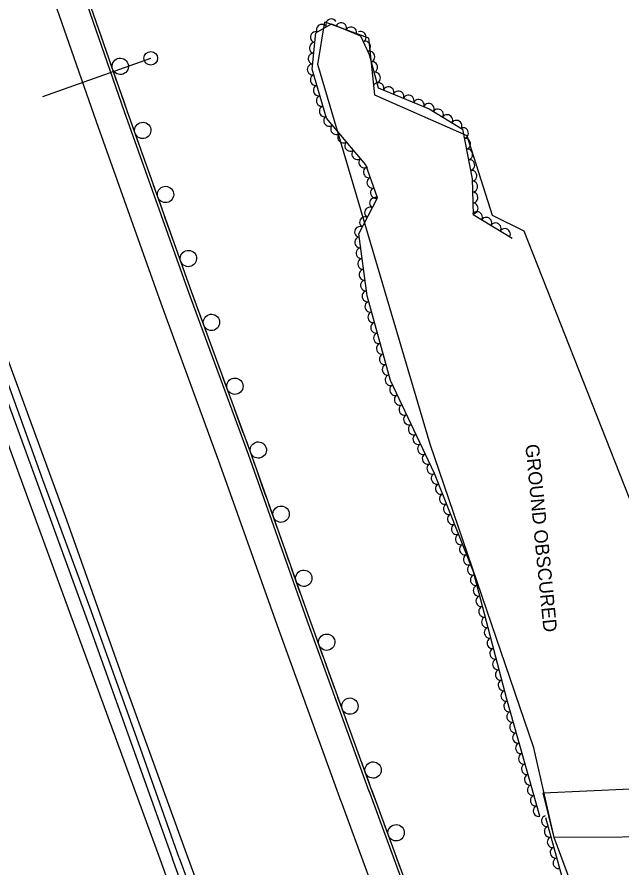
# Model space of a CAD drawing. Extents: x 1746719 to 1766531, y 631721 to 662391.
# Drawn here: x 1754457 to 1754679.2, y 649456.3 to 649768.8 of the extents above; entities that cross this region are included whole.
import ezdxf

# ---------------------------------------------------------------- set-up
doc = ezdxf.new("R2010")
doc.units = 0
for name, color, linetype in [('SURVEY - AERIAL SURVEY - Photo Control - Points - Elevations', 7, 'Continuous'), ('SURVEY - AERIAL SURVEY - Photo Control - Points - Locators', 7, 'Continuous'), ('SURVEY - AERIAL SURVEY - Photo Control - Points - Numbers', 7, 'Continuous'), ('SURVEY - AERIAL SURVEY - Photo Control with Text', 7, 'Continuous'), ('SURVEY - CONTROL - Grid', 7, 'Continuous')]:
    doc.layers.add(name, color=color, linetype=linetype)

msp = doc.modelspace()

# ---------------------------------------------------------------- linework, layer by layer
at = {"layer": 'SURVEY - AERIAL SURVEY - Photo Control - Points - Elevations'}
for points in [[(1754372.91, 649841.05), (1754399.86, 649762.15), (1754431.05, 649673.76), (1754457.17, 649602.22), (1754509.57, 649459.27)], [(1754519.88, 649459.84), (1754496.93, 649522.97), (1754475.36, 649583.78), (1754453.6, 649643.04), (1754429.6, 649710.4), (1754402.92, 649787.27), (1754386.52, 649835.23)], [(1754576.27, 649480.33), (1754553.4, 649543.24), (1754531.8, 649604.15), (1754510.02, 649663.45), (1754486.2, 649730.31), (1754460.8, 649803.48)], [(1754586.6, 649484.09), (1754563.76, 649546.96), (1754542.15, 649607.89), (1754520.37, 649667.19), (1754496.58, 649733.96), (1754474.48, 649797.64)], [(1755115.35, 648210.44), (1755101.05, 648241.68), (1755075.7, 648298.73), (1755049.35, 648357.31), (1755030.85, 648399.58), (1755014.73, 648435.52), (1754992.75, 648485.36), (1754969, 648539.7), (1754947.21, 648588.87), (1754915.3, 648661.1), (1754893.71, 648710.14), (1754872.45, 648759.46), (1754844.58, 648825.55), (1754823.17, 648877.77), (1754798.13, 648938.26), (1754769.55, 649009.24), (1754747.62, 649063.55), (1754724.17, 649123.36), (1754701.64, 649181.06), (1754680.19, 649235.39), (1754656.46, 649296.06), (1754637.62, 649345.88), (1754614.74, 649407.39), (1754586.53, 649484.29)], [(1755104.99, 648205.74), (1755065.66, 648294.24), (1755039.29, 648352.85), (1755020.79, 648395.13), (1755004.68, 648431.05), (1754982.68, 648480.94), (1754958.93, 648535.27), (1754937.15, 648584.41), (1754905.24, 648656.66), (1754883.62, 648705.74), (1754862.33, 648755.14), (1754834.42, 648821.33), (1754813, 648873.58), (1754787.94, 648934.1), (1754759.35, 649005.13), (1754737.4, 649059.49), (1754713.93, 649119.35), (1754691.4, 649177.04), (1754669.95, 649231.36), (1754646.2, 649292.11), (1754627.32, 649342.01), (1754604.42, 649403.58), (1754576.2, 649480.5)], [(1754509.57, 649459.27), (1754525.94, 649413.69), (1754546.16, 649358.93), (1754566.55, 649304.57), (1754591.05, 649240.64), (1754617.15, 649173.14), (1754643.97, 649105.23), (1754664.59, 649052.46), (1754685.99, 648998.63), (1754712.43, 648932.12), (1754736.99, 648873.55), (1754758.79, 648818.39), (1754779.59, 648768.19), (1754804.48, 648710.45), (1754831.65, 648646.67), (1754855.43, 648592.01), (1754875.72, 648544.86), (1754897.72, 648495.75)], [(1755048.84, 648185.15), (1755036.33, 648212.5), (1755010.89, 648269.75), (1754984.45, 648328.51), (1754965.93, 648370.82), (1754949.86, 648406.67), (1754927.74, 648456.82), (1754904.02, 648511.09), (1754882.28, 648560.14), (1754850.34, 648632.45), (1754828.62, 648681.78), (1754807.13, 648731.61), (1754779.02, 648798.3), (1754757.53, 648850.72), (1754732.4, 648911.42), (1754703.7, 648982.69), (1754681.66, 649037.3), (1754658.05, 649097.48), (1754635.55, 649155.11), (1754614.11, 649209.42), (1754590.2, 649270.57), (1754571.14, 649320.94), (1754548.14, 649382.79), (1754519.88, 649459.84)]]:
    msp.add_lwpolyline(points, dxfattribs=at)
at = {"layer": 'SURVEY - AERIAL SURVEY - Photo Control - Points - Locators'}
for points in [[(1754643.48, 649690.19), (1754713.8, 649511.77), (1754691.9, 649508.23), (1754704.69, 649467.42), (1754654.55, 649467.07), (1754647.16, 649500.04), (1754608.95, 649611.71), (1754567.7, 649751.34), (1754570.28, 649767.07), (1754586.25, 649761.13), (1754588.45, 649740.16), (1754622.5, 649725.22), (1754631.78, 649695.88), (1754643.48, 649690.19)], [(1754682.93, 649401.74), (1754668.94, 649428.44), (1754654.55, 649467.07), (1754654.55, 649467.07), (1754650.58, 649483.59), (1754698.72, 649485.75)]]:
    msp.add_lwpolyline(points, dxfattribs=at)
at = {"layer": 'SURVEY - AERIAL SURVEY - Photo Control - Points - Numbers'}
for points in [[(1754379.58, 649838.2), (1754396.39, 649787.83), (1754417.71, 649728.02), (1754438.48, 649668.45), (1754465.02, 649595.86), (1754484.29, 649542.97), (1754514.24, 649459.31)], [(1754516.62, 649459.65), (1754501.04, 649503.67), (1754483.8, 649551.83), (1754466.56, 649598.63), (1754446.68, 649653.43), (1754425.68, 649712.01), (1754407.27, 649765.12), (1754389.44, 649816.85), (1754382.87, 649836.79)], [(1754587.54, 649484.43), (1754564.7, 649547.3), (1754543.09, 649608.22), (1754521.31, 649667.53), (1754497.52, 649734.29), (1754475.72, 649797.1)], [(1754488.06, 649761.54), (1754486.52, 649765.98)], [(1754489.6, 649757.1), (1754488.06, 649761.54)], [(1754493.67, 649745.39), (1754490.65, 649754.08)], [(1754496.26, 649737.92), (1754494.72, 649742.36)], [(1754497.81, 649733.48), (1754497.52, 649734.29), (1754496.26, 649737.92)], [(1754501.97, 649721.81), (1754498.88, 649730.47)], [(1754504.62, 649714.36), (1754503.04, 649718.79)], [(1754506.2, 649709.94), (1754504.62, 649714.36)], [(1754510.36, 649698.26), (1754507.27, 649706.92)], [(1754513.01, 649690.81), (1754511.43, 649695.24)], [(1754514.59, 649686.39), (1754513.01, 649690.81)], [(1754518.75, 649674.71), (1754515.66, 649683.37)], [(1754521.41, 649667.27), (1754521.31, 649667.53), (1754519.82, 649671.69)], [(1754523.03, 649662.85), (1754521.41, 649667.27)], [(1754527.3, 649651.21), (1754524.13, 649659.85)], [(1754530.02, 649643.8), (1754528.4, 649648.21)], [(1754531.64, 649639.39), (1754530.02, 649643.8)], [(1754535.92, 649627.75), (1754532.75, 649636.38)], [(1754538.64, 649620.33), (1754537.02, 649624.74)], [(1754540.26, 649615.92), (1754538.64, 649620.33)], [(1754544.49, 649604.26), (1754543.09, 649608.22), (1754541.37, 649612.91)], [(1754547.13, 649596.82), (1754545.56, 649601.25)], [(1754548.71, 649592.39), (1754547.13, 649596.82)], [(1754552.85, 649580.7), (1754549.78, 649589.37)], [(1754555.49, 649573.26), (1754553.92, 649577.69)], [(1754557.06, 649568.83), (1754555.49, 649573.26)], [(1754561.21, 649557.14), (1754558.13, 649565.81)], [(1754563.85, 649549.69), (1754562.28, 649554.12)], [(1754565.44, 649545.27), (1754564.7, 649547.3), (1754563.85, 649549.69)], [(1754569.67, 649533.61), (1754566.53, 649542.26)], [(1754572.37, 649526.19), (1754570.76, 649530.61)], [(1754573.97, 649521.77), (1754572.37, 649526.19)], [(1754578.21, 649510.12), (1754575.07, 649518.77)], [(1754580.91, 649502.69), (1754579.3, 649507.11)], [(1754582.51, 649498.28), (1754580.91, 649502.69)], [(1754586.75, 649486.62), (1754583.61, 649495.27)], [(1754825.74, 648874.19), (1754799.05, 648938.64), (1754770.48, 649009.61), (1754748.55, 649063.92), (1754725.1, 649123.72), (1754702.57, 649181.43), (1754681.12, 649235.75), (1754657.4, 649296.42), (1754638.55, 649346.23), (1754615.68, 649407.74), (1754587.47, 649484.64)], [(1754589.31, 649479.61), (1754587.7, 649484.02)], [(1754590.93, 649475.2), (1754589.31, 649479.61)], [(1754595.2, 649463.56), (1754592.03, 649472.19)], [(1754657.78, 649084.72), (1754651.77, 649095.7), (1754644.91, 649114.57), (1754640.02, 649129.04), (1754621.89, 649173.71), (1754602.64, 649223.49), (1754583.25, 649272.46), (1754564.88, 649320.62), (1754549.66, 649361.58), (1754514.24, 649459.31)], [(1754516.62, 649459.65), (1754532.02, 649417.92), (1754562.15, 649336.06), (1754590.13, 649262.94), (1754616.89, 649194.61), (1754640.12, 649134.36), (1754645.92, 649119.41), (1754651.12, 649109.65), (1754655.75, 649097.16), (1754660.99, 649082.25), (1754673.09, 649051.95), (1754687.64, 649015.48), (1754717.9, 648940.22), (1754739.62, 648887.08), (1754769.78, 648812.67)], [(1754597.92, 649456.14), (1754596.3, 649460.55)]]:
    msp.add_lwpolyline(points, dxfattribs=at)
for centre, start, end in [((1754495.01, 649750.67), 312.4083, 312.3943), ((1754503.26, 649727.1), 312.8809, 312.8669), ((1754511.66, 649703.55), 312.8809, 312.8669), ((1754520.05, 649680), 312.8809, 312.8669), ((1754528.55, 649656.52), 313.4349, 313.4209), ((1754537.16, 649633.06), 313.4349, 313.4209), ((1754545.78, 649609.59), 313.4349, 313.4209), ((1754554.15, 649586), 312.7969, 312.783), ((1754562.51, 649562.43), 312.7969, 312.783), ((1754570.93, 649538.92), 313.241, 313.227), ((1754579.47, 649515.42), 313.241, 313.227), ((1754588.01, 649491.93), 313.241, 313.227), ((1754596.45, 649468.87), 313.4136, 313.3996)]:
    msp.add_arc(centre, 3, start, end, dxfattribs=at)
at = {"layer": 'SURVEY - AERIAL SURVEY - Photo Control with Text'}
for points in [[(1754649.35, 649474.93), (1754637.21, 649517.97), (1754624.87, 649564.86), (1754610.53, 649600.97), (1754594.36, 649635.14), (1754585.79, 649666.28), (1754582.72, 649689.04), (1754589.58, 649702.3), (1754585.35, 649714.48), (1754570.82, 649731.65), (1754565.64, 649749.67), (1754566.99, 649762.94), (1754572.68, 649766.24), (1754583.34, 649761.85), (1754586.52, 649754.97), (1754589.81, 649742.81), (1754608.59, 649735.03), (1754620.88, 649727.57), (1754624.49, 649709.33), (1754624.76, 649696.21), (1754639.18, 649687.45)], [(1754680.76, 649396.69), (1754667.56, 649416.66), (1754657.4, 649453), (1754651.48, 649474.32)]]:
    msp.add_lwpolyline(points, dxfattribs=at)
for centre, major_axis in [((1754572.58, 649766.18), (1.73, 1)), ((1754569.12, 649764.18), (1.73, 1)), ((1754576.27, 649764.76), (1.85, -0.76)), ((1754579.97, 649763.23), (1.85, -0.76)), ((1754566.83, 649761.42), (0.2, 1.99)), ((1754583.49, 649761.52), (0.84, -1.82)), ((1754566.43, 649757.44), (0.2, 1.99)), ((1754585.17, 649757.89), (0.84, -1.82)), ((1754566.02, 649753.46), (0.2, 1.99)), ((1754586.73, 649754.22), (0.52, -1.93)), ((1754587.77, 649750.36), (0.52, -1.93)), ((1754565.69, 649749.48), (-0.55, 1.92)), ((1754566.8, 649745.64), (-0.55, 1.92)), ((1754588.81, 649746.49), (0.52, -1.93)), ((1754567.9, 649741.8), (-0.55, 1.92)), ((1754589.98, 649742.74), (1.85, -0.77)), ((1754593.67, 649741.21), (1.85, -0.77)), ((1754569.01, 649737.95), (-0.55, 1.92)), ((1754597.37, 649739.68), (1.85, -0.77)), ((1754601.07, 649738.15), (1.85, -0.77)), ((1754604.76, 649736.62), (1.85, -0.77)), ((1754608.46, 649735.09), (1.85, -0.77)), ((1754570.11, 649734.11), (-0.55, 1.92)), ((1754611.89, 649733.03), (1.71, -1.04)), ((1754615.3, 649730.96), (1.71, -1.04)), ((1754571.75, 649730.55), (-1.29, 1.53)), ((1754618.72, 649728.88), (1.71, -1.04)), ((1754574.34, 649727.49), (-1.29, 1.53)), ((1754621.17, 649726.12), (0.39, -1.96)), ((1754576.92, 649724.44), (-1.29, 1.53)), ((1754621.94, 649722.2), (0.39, -1.96)), ((1754579.5, 649721.39), (-1.29, 1.53)), ((1754582.09, 649718.33), (-1.29, 1.53)), ((1754622.72, 649718.27), (0.39, -1.96)), ((1754584.67, 649715.28), (-1.29, 1.53)), ((1754623.5, 649714.35), (0.39, -1.96)), ((1754586.32, 649711.69), (-0.66, 1.89)), ((1754624.27, 649710.43), (0.39, -1.96)), ((1754587.63, 649707.91), (-0.66, 1.89)), ((1754624.55, 649706.45), (0.04, -2)), ((1754588.94, 649704.14), (-0.66, 1.89)), ((1754588.64, 649700.47), (0.92, 1.78)), ((1754624.63, 649702.45), (0.04, -2)), ((1754586.8, 649696.92), (0.92, 1.78)), ((1754624.71, 649698.45), (0.04, -2)), ((1754584.96, 649693.37), (0.92, 1.78)), ((1754626.26, 649695.3), (1.71, -1.04)), ((1754629.68, 649693.22), (1.71, -1.04)), ((1754633.1, 649691.15), (1.71, -1.04)), ((1754583.12, 649689.82), (0.92, 1.78)), ((1754636.52, 649689.07), (1.71, -1.04)), ((1754583.14, 649685.94), (-0.27, 1.98)), ((1754583.67, 649681.98), (-0.27, 1.98)), ((1754584.21, 649678.01), (-0.27, 1.98)), ((1754584.74, 649674.05), (-0.27, 1.98)), ((1754585.28, 649670.08), (-0.27, 1.98)), ((1754585.83, 649666.12), (-0.53, 1.93)), ((1754586.89, 649662.27), (-0.53, 1.93)), ((1754587.96, 649658.41), (-0.53, 1.93)), ((1754589.02, 649654.55), (-0.53, 1.93)), ((1754590.08, 649650.7), (-0.53, 1.93)), ((1754591.14, 649646.84), (-0.53, 1.93)), ((1754592.2, 649642.98), (-0.53, 1.93)), ((1754593.26, 649639.13), (-0.53, 1.93)), ((1754594.32, 649635.27), (-0.53, 1.93)), ((1754596.01, 649631.65), (-0.86, 1.81)), ((1754597.72, 649628.03), (-0.86, 1.81)), ((1754599.43, 649624.42), (-0.86, 1.81)), ((1754601.14, 649620.8), (-0.86, 1.81)), ((1754602.86, 649617.18), (-0.86, 1.81)), ((1754604.57, 649613.57), (-0.86, 1.81)), ((1754606.28, 649609.95), (-0.86, 1.81)), ((1754607.99, 649606.34), (-0.86, 1.81)), ((1754609.7, 649602.72), (-0.86, 1.81)), ((1754611.29, 649599.05), (-0.74, 1.86)), ((1754612.77, 649595.34), (-0.74, 1.86)), ((1754614.24, 649591.62), (-0.74, 1.86)), ((1754615.72, 649587.9), (-0.74, 1.86)), ((1754617.19, 649584.18), (-0.74, 1.86)), ((1754618.67, 649580.47), (-0.74, 1.86)), ((1754620.15, 649576.75), (-0.74, 1.86)), ((1754621.62, 649573.03), (-0.74, 1.86)), ((1754623.1, 649569.31), (-0.74, 1.86)), ((1754624.58, 649565.6), (-0.74, 1.86)), ((1754625.69, 649561.76), (-0.51, 1.93)), ((1754626.7, 649557.89), (-0.51, 1.93)), ((1754627.72, 649554.02), (-0.51, 1.93)), ((1754628.74, 649550.15), (-0.51, 1.93)), ((1754629.76, 649546.28), (-0.51, 1.93)), ((1754630.78, 649542.42), (-0.51, 1.93)), ((1754631.8, 649538.55), (-0.51, 1.93)), ((1754632.81, 649534.68), (-0.51, 1.93)), ((1754633.83, 649530.81), (-0.51, 1.93)), ((1754634.85, 649526.94), (-0.51, 1.93)), ((1754635.87, 649523.08), (-0.51, 1.93)), ((1754636.89, 649519.21), (-0.51, 1.93)), ((1754637.95, 649515.35), (-0.54, 1.92)), ((1754639.04, 649511.5), (-0.54, 1.92)), ((1754640.12, 649507.65), (-0.54, 1.92)), ((1754641.21, 649503.8), (-0.54, 1.92)), ((1754642.29, 649499.95), (-0.54, 1.92)), ((1754643.38, 649496.1), (-0.54, 1.92)), ((1754644.46, 649492.25), (-0.54, 1.92)), ((1754645.55, 649488.4), (-0.54, 1.92)), ((1754646.63, 649484.55), (-0.54, 1.92)), ((1754647.72, 649480.7), (-0.54, 1.92)), ((1754648.8, 649476.85), (-0.54, 1.92)), ((1754651.81, 649473.13), (-0.54, 1.93)), ((1754652.88, 649469.27), (-0.54, 1.93)), ((1754653.95, 649465.42), (-0.54, 1.93)), ((1754655.02, 649461.57), (-0.54, 1.93)), ((1754656.09, 649457.71), (-0.54, 1.93))]:
    msp.add_ellipse(centre, major_axis=major_axis, ratio=0.940188, start_param=0, end_param=3.141593, dxfattribs=at)
at = {"layer": 'SURVEY - CONTROL - Grid'}
for p, q in [((1754466.48, 649739.59), (1754506.21, 649753.62)), ((1754506.2, 649753.6), (1754506.2, 649753.6))]:
    msp.add_line(p, q, dxfattribs=at)
msp.add_circle((1754506.21, 649753.62), 2.5, dxfattribs=at)

# ---------------------------------------------------------------- texts
at = {"layer": 'SURVEY - AERIAL SURVEY - Photo Control - Points - Locators'}
msp.add_text('GROUND OBSCURED', height=5, rotation=275.6107, dxfattribs=at).set_placement((1754643.97, 649611.53))

doc.saveas('drawing.dxf')
